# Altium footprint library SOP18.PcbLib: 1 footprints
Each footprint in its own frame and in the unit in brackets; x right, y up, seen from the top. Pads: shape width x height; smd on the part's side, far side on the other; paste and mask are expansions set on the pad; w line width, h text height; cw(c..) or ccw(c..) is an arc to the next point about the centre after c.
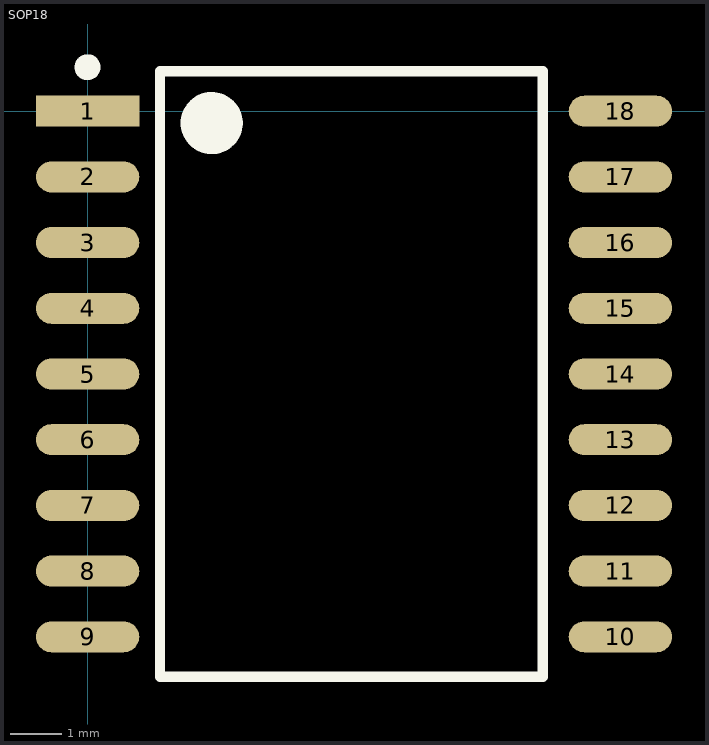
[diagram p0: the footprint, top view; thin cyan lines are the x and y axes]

## SOP18 [mm] "SOP, 18-Leads, Body 11.7x7.6mm (max), Pitch 1.27mm, IPC Medium Density"
height 2.6
pads (18):
  rect 2x0.6 smd: 1(0,0)
  oval 2x0.6 smd: 2(0,-1.27) 3(0,-2.54) 4(0,-3.81) 5(0,-5.08) 6(0,-6.35) 7(0,-7.62) 8(0,-8.89) 9(0,-10.16) 10(10.3,-10.16) 11(10.3,-8.89) 12(10.3,-7.62) 13(10.3,-6.35) 14(10.3,-5.08) 15(10.3,-3.81) 16(10.3,-2.54) 17(10.3,-1.27) 18(10.3,0)
Top Overlay:
  circle w0.25: c0,0.85 r0.125
  circle w0.6: c2.4,-0.23 r0.3
  lines w0.2: 1.4,-10.93 1.4,0.77 8.8,0.77 8.8,-10.93 1.4,-10.93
